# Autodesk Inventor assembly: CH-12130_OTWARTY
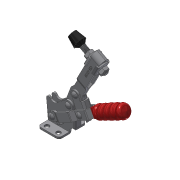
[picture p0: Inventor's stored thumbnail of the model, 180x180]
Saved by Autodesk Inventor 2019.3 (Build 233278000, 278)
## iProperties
Company: Î¢ÈíÖÐ¹ú
Created: 2012-09
Part Number: CH-12130_OTWARTY
Material: Ogólny
Description: STEP AP203
Document SubType Name: Assembly
Designer: CADENGINEERING4
Sending System: SolidWorks 2010
Preprocessor: SwSTEP 2.0
Title: CH-12130.STEP
Author: Î¢ÈíÓÃ»§
Revision Number: ÈÎºÎ
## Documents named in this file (12)
- D:\Vault_2016\Projekty\NASZ KATALOG\CLAMPTEK\STRONA\Vertical toggle clamp\CH-12130\CH-12130_OTWARTY.iam
- D:\Vault_2016\Projekty\NASZ KATALOG\CLAMPTEK\STEP FILES\Vertical toggle clamp\CH-12130\CH-FC-56212 Nut.ipt
- D:\Vault_2016\Projekty\NASZ KATALOG\CLAMPTEK\STEP FILES\Vertical toggle clamp\CH-12130\CH-12130-06.ipt
- D:\Vault_2016\Projekty\NASZ KATALOG\CLAMPTEK\STEP FILES\Vertical toggle clamp\CH-12130\CH-FW-516.ipt
- D:\Vault_2016\Projekty\NASZ KATALOG\CLAMPTEK\STEP FILES\Vertical toggle clamp\CH-12130\CH-12130-03 STRAIGHT HANDLE.ipt
- D:\Vault_2016\Projekty\NASZ KATALOG\CLAMPTEK\STEP FILES\Vertical toggle clamp\CH-12130\CH-12130-08.ipt
- D:\Vault_2016\Projekty\NASZ KATALOG\CLAMPTEK\STEP FILES\Vertical toggle clamp\CH-12130\CH-12130-07.ipt
- D:\Vault_2016\Projekty\NASZ KATALOG\CLAMPTEK\STEP FILES\Vertical toggle clamp\CH-12130\CH-12130-04 CONNECTING-PLATE.ipt
- D:\Vault_2016\Projekty\NASZ KATALOG\CLAMPTEK\STEP FILES\Vertical toggle clamp\CH-12130\CH-12130-05.ipt
- D:\Vault_2016\Projekty\NASZ KATALOG\CLAMPTEK\STEP FILES\Vertical toggle clamp\CH-12130\CH-12130-02 SHORT U-BAR.ipt
- D:\Vault_2016\Projekty\NASZ KATALOG\CLAMPTEK\STEP FILES\Vertical toggle clamp\CH-12130\CH-12130-01 FLANGED BASE.ipt
- D:\Vault_2016\Projekty\NASZ KATALOG\CLAMPTEK\STEP FILES\Vertical toggle clamp\CH-12130\CH-FC-56212 SPINDLE SUPPLIED.ipt
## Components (15 placed, 11 different names)
1. CH-12130-01 FLANGED BASE_14
2. CH-FC-56212 Nut:3 — Zestawiające:22, Zestawiające:23, Zestawiające:24, Zestawiające:28, Zestawiające:30, Zestawiające:31
3. CH-12130-06:3 — Zestawiające:9, Zestawiające:10
4. CH-FC-56212 Nut:4 — Zestawiające:21, Zestawiające:22, Zestawiające:27
5. CH-FW-516:3 — Zestawiające:24, Zestawiające:25, Zestawiające:27, Równoległe:3
6. CH-12130-03 STRAIGHT HANDLE:2 — Zestawiające:4, Zestawiające:11, Zestawiające:14, Zestawiające:16, Zestawiające:17, Zestawiające:18, Zestawiające:19, Zestawiające:20, Zestawiające:29
7. CH-12130-08:3 — Zestawiające:13, Zestawiające:14, Zestawiające:15, Zestawiające:16, Zestawiające:17
8. CH-12130-07:2 — Zestawiające:18, Zestawiające:19, Zestawiające:20
9. CH-12130-06:4 — Zestawiające:5, Zestawiające:6, Zestawiające:7, Zestawiające:8
10. CH-12130-04 CONNECTING-PLATE:2 — Zestawiające:5, Zestawiające:7, Zestawiające:8, Zestawiające:10, Zestawiające:11, Zestawiające:12, Zestawiające:13, Zestawiające:15
11. CH-12130-05:2 — Zestawiające:1, Zestawiające:2, Zestawiające:3, Równoległe:1
12. CH-12130-02 SHORT U-BAR:2 — Równoległe:1, Zestawiające:6, Zestawiające:9, Zestawiające:12, Zestawiające:25, Zestawiające:26, Równoległe:2, Kątowe:1, Zestawiające:30, Zestawiające:31
13. CH-FW-516:4 — Zestawiające:23, Zestawiające:26, Zestawiające:28, Równoległe:3, Kątowe:1
14. CH-12130-08:4 — Zestawiające:1, Zestawiające:2, Zestawiające:3, Zestawiające:4, Zestawiające:29
15. CH-FC-56212 SPINDLE SUPPLIED:2 — Zestawiające:21, Równoległe:2
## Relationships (35: Mate 31, Flush 3, Angle 1)
- Zestawiające:1 [Mate]: CH-12130-05:2 ↔ CH-12130-08:4
- Zestawiające:2 [Mate]: CH-12130-05:2 ↔ CH-12130-08:4
- Zestawiające:3 [Mate]: CH-12130-05:2 ↔ CH-12130-08:4
- Zestawiające:4 [Mate]: CH-12130-03 STRAIGHT HANDLE:2 ↔ CH-12130-08:4
- Równoległe:1 [Flush]: CH-12130-05:2 ↔ CH-12130-02 SHORT U-BAR:2
- Zestawiające:5 [Mate]: CH-12130-06:4 ↔ CH-12130-04 CONNECTING-PLATE:2
- Zestawiające:6 [Mate]: CH-12130-06:4 ↔ CH-12130-02 SHORT U-BAR:2
- Zestawiające:7 [Mate]: CH-12130-06:4 ↔ CH-12130-04 CONNECTING-PLATE:2
- Zestawiające:8 [Mate]: CH-12130-06:4 ↔ CH-12130-04 CONNECTING-PLATE:2
- Zestawiające:9 [Mate]: CH-12130-06:3 ↔ CH-12130-02 SHORT U-BAR:2
- Zestawiające:10 [Mate]: CH-12130-06:3 ↔ CH-12130-04 CONNECTING-PLATE:2
- Zestawiające:11 [Mate]: CH-12130-03 STRAIGHT HANDLE:2 ↔ CH-12130-04 CONNECTING-PLATE:2
- Zestawiające:12 [Mate]: CH-12130-04 CONNECTING-PLATE:2 ↔ CH-12130-02 SHORT U-BAR:2
- Zestawiające:13 [Mate]: CH-12130-08:3 ↔ CH-12130-04 CONNECTING-PLATE:2
- Zestawiające:14 [Mate]: CH-12130-03 STRAIGHT HANDLE:2 ↔ CH-12130-08:3
- Zestawiające:15 [Mate]: CH-12130-08:3 ↔ CH-12130-04 CONNECTING-PLATE:2
- Zestawiające:16 [Mate]: CH-12130-03 STRAIGHT HANDLE:2 ↔ CH-12130-08:3
- Zestawiające:17 [Mate]: CH-12130-03 STRAIGHT HANDLE:2 ↔ CH-12130-08:3
- Zestawiające:18 [Mate]: CH-12130-03 STRAIGHT HANDLE:2 ↔ CH-12130-07:2
- Zestawiające:19 [Mate]: CH-12130-03 STRAIGHT HANDLE:2 ↔ CH-12130-07:2
- Zestawiające:20 [Mate]: CH-12130-03 STRAIGHT HANDLE:2 ↔ CH-12130-07:2
- Zestawiające:21 [Mate]: CH-FC-56212 Nut:4 ↔ CH-FC-56212 SPINDLE SUPPLIED:2
- Zestawiające:22 [Mate]: CH-FC-56212 Nut:3 ↔ CH-FC-56212 Nut:4
- Zestawiające:23 [Mate]: CH-FC-56212 Nut:3 ↔ CH-FW-516:4
- Zestawiające:24 [Mate]: CH-FC-56212 Nut:3 ↔ CH-FW-516:3
- Zestawiające:25 [Mate]: CH-FW-516:3 ↔ CH-12130-02 SHORT U-BAR:2
- Zestawiające:26 [Mate]: CH-12130-02 SHORT U-BAR:2 ↔ CH-FW-516:4
- Zestawiające:27 [Mate]: CH-FC-56212 Nut:4 ↔ CH-FW-516:3
- Zestawiające:28 [Mate]: CH-FC-56212 Nut:3 ↔ CH-FW-516:4
- Równoległe:2 [Flush]: CH-12130-02 SHORT U-BAR:2 ↔ CH-FC-56212 SPINDLE SUPPLIED:2
- Równoległe:3 [Flush]: CH-FW-516:3 ↔ CH-FW-516:4
- Kątowe:1 [Angle]: CH-12130-02 SHORT U-BAR:2 ↔ CH-FW-516:4
- Zestawiające:29 [Mate]: CH-12130-03 STRAIGHT HANDLE:2 ↔ CH-12130-08:4
- Zestawiające:30 [Mate]: CH-FC-56212 Nut:3 ↔ CH-12130-02 SHORT U-BAR:2
- Zestawiające:31 [Mate]: CH-FC-56212 Nut:3 ↔ CH-12130-02 SHORT U-BAR:2
